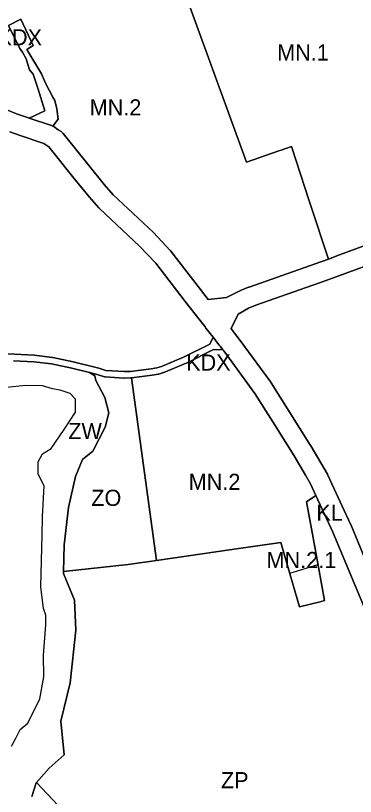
# Model space of a CAD drawing. Extents: x 7431767 to 7433133, y 5549450 to 5550702.
# Drawn here: x 7432224.9 to 7432434.9, y 5549892.8 to 5550375.6 of the extents above; entities that cross this region are included whole.
import ezdxf

# ---------------------------------------------------------------- set-up
doc = ezdxf.new("R2010")
doc.units = 0
for name, color, linetype in [('linie_rozgraniczajace', 7, 'Continuous'), ('nieprzekraczalne_linie_zabudowy', 7, 'Continuous'), ('oznaczenia_przeznaczen', 7, 'Continuous')]:
    doc.layers.add(name, color=color, linetype=linetype)

msp = doc.modelspace()

# ---------------------------------------------------------------- linework, layer by layer
at = {"layer": 'linie_rozgraniczajace'}
for points in [[(7432324.79, 5550402.95), (7432367.6, 5550285.01), (7432387.65, 5550291.96), (7432389, 5550292.48), (7432395.45, 5550294.68), (7432406.26, 5550261.15), (7432418.17, 5550225.09), (7432410.03, 5550222.13), (7432369.14, 5550207.78), (7432368.84, 5550207.66), (7432363.79, 5550205.54), (7432363.61, 5550205.45), (7432363.12, 5550205.2), (7432355.18, 5550201.22), (7432343.93, 5550200.14), (7432339.15, 5550206.28), (7432320.83, 5550229.98), (7432320.57, 5550230.29), (7432320.47, 5550230.4), (7432310.2, 5550241.47), (7432310.04, 5550241.57), (7432309.91, 5550241.77), (7432285.14, 5550264.86), (7432279.66, 5550271.15), (7432270.25, 5550282.69), (7432254.3, 5550302.65), (7432253.68, 5550303.31), (7432253, 5550303.85), (7432251.27, 5550305.05), (7432248.53, 5550306.94), (7432247.86, 5550307.3), (7432251.1, 5550311.5), (7432250.4, 5550317.93), (7432249.03, 5550323.1), (7432247.98, 5550325.07), (7432243.38, 5550333.82), (7432240.92, 5550339.61), (7432231.81, 5550354.58), (7432235.73, 5550357.2), (7432228.13, 5550373.41), (7432220.5, 5550369.5), (7432227.46, 5550355.28), (7432229.18, 5550353.02), (7432231.35, 5550348.97), (7432233.41, 5550342.08), (7432235.68, 5550339.37), (7432238.59, 5550330.8), (7432242.97, 5550316.77), (7432233.24, 5550312.23), (7432231.53, 5550312.79), (7432225.41, 5550314.91), (7432219.55, 5550317.43)], [(7432441.37, 5550233.57), (7432425.1, 5550227.62), (7432418.17, 5550225.09), (7432406.26, 5550261.15), (7432395.45, 5550294.68), (7432389, 5550292.48), (7432387.65, 5550291.96), (7432367.6, 5550285.01), (7432324.79, 5550402.95)], [(7432219.55, 5550317.43), (7432225.41, 5550314.91), (7432231.53, 5550312.79), (7432233.24, 5550312.23), (7432247.06, 5550307.65), (7432247.86, 5550307.3), (7432248.53, 5550306.94), (7432251.27, 5550305.05), (7432253, 5550303.85), (7432253.68, 5550303.31), (7432254.3, 5550302.65), (7432270.25, 5550282.69), (7432279.66, 5550271.15), (7432285.14, 5550264.86), (7432309.91, 5550241.77), (7432310.04, 5550241.57), (7432310.2, 5550241.47), (7432320.47, 5550230.4), (7432320.57, 5550230.29)], [(7432221.27, 5550303.64), (7432227.64, 5550301.44), (7432242.42, 5550296.57), (7432245.47, 5550294.46), (7432260.89, 5550275.17), (7432270.43, 5550263.49), (7432270.53, 5550263.4), (7432276.28, 5550256.75), (7432276.7, 5550256.31), (7432301.56, 5550233.14), (7432311.51, 5550222.43), (7432329.66, 5550198.92), (7432341.17, 5550184.28), (7432341.99, 5550183.21), (7432342.53, 5550182.4), (7432346.91, 5550176.76), (7432344.87, 5550172.53), (7432328.69, 5550164.34), (7432314.97, 5550158.64), (7432312.25, 5550157.75), (7432308.68, 5550157.2), (7432295.92, 5550155.63), (7432291.89, 5550155.47), (7432280.73, 5550156.25), (7432276.36, 5550157.51), (7432260.53, 5550161.53), (7432247.85, 5550164.21), (7432247.69, 5550164.24), (7432236.38, 5550165.6), (7432220.02, 5550166.42)], [(7432420.95, 5550056.23), (7432410.46, 5550078.85), (7432407.07, 5550086.17), (7432403.98, 5550091.44), (7432396.96, 5550103.47), (7432383.88, 5550124.43), (7432372.75, 5550141.96), (7432353.55, 5550168.26), (7432353.02, 5550168.97), (7432351.3, 5550171.29), (7432350.68, 5550171.93), (7432348.7, 5550174.47), (7432346.91, 5550176.76), (7432342.53, 5550182.4), (7432341.99, 5550183.21), (7432341.17, 5550184.28), (7432329.66, 5550198.92), (7432311.51, 5550222.43), (7432301.56, 5550233.14), (7432276.7, 5550256.31), (7432276.28, 5550256.75), (7432270.53, 5550263.4), (7432270.43, 5550263.49), (7432260.89, 5550275.17), (7432245.47, 5550294.46), (7432242.42, 5550296.57), (7432227.64, 5550301.44), (7432221.27, 5550303.64)], [(7432320.57, 5550230.29), (7432320.83, 5550229.98), (7432339.15, 5550206.28), (7432343.93, 5550200.14), (7432355.18, 5550201.22), (7432363.12, 5550205.2), (7432363.61, 5550205.45), (7432363.79, 5550205.54), (7432368.84, 5550207.66), (7432369.14, 5550207.78), (7432410.03, 5550222.13), (7432418.17, 5550225.09), (7432425.1, 5550227.62), (7432441.37, 5550233.57)], [(7432445.39, 5550222.28), (7432416.21, 5550211.58), (7432373.29, 5550196.52), (7432368.8, 5550194.63), (7432362.38, 5550190.91), (7432358.05, 5550182.04), (7432359.57, 5550180.09), (7432360.17, 5550179.31), (7432363.1, 5550175.49), (7432382.57, 5550148.88), (7432382.67, 5550148.68), (7432382.77, 5550148.55), (7432394.03, 5550130.84), (7432407.21, 5550109.75), (7432407.28, 5550109.6), (7432417.56, 5550091.97), (7432417.83, 5550091.48), (7432431.88, 5550061.17), (7432431.99, 5550060.95), (7432450.91, 5550015.4)], [(7432450.91, 5550015.4), (7432431.99, 5550060.95), (7432431.88, 5550061.17), (7432417.83, 5550091.48), (7432417.56, 5550091.97), (7432407.28, 5550109.6), (7432407.21, 5550109.75), (7432394.03, 5550130.84), (7432382.77, 5550148.55), (7432382.67, 5550148.68), (7432382.57, 5550148.88), (7432363.1, 5550175.49), (7432360.17, 5550179.31), (7432359.57, 5550180.09), (7432358.05, 5550182.04), (7432362.38, 5550190.91), (7432368.8, 5550194.63), (7432373.29, 5550196.52), (7432416.21, 5550211.58), (7432445.39, 5550222.28)], [(7432220.02, 5550166.42), (7432236.38, 5550165.6), (7432247.69, 5550164.24), (7432247.85, 5550164.21), (7432260.53, 5550161.53), (7432276.36, 5550157.51), (7432280.73, 5550156.25), (7432291.89, 5550155.47), (7432295.92, 5550155.63), (7432308.68, 5550157.2), (7432312.25, 5550157.75), (7432314.97, 5550158.64), (7432328.69, 5550164.34), (7432344.87, 5550172.53), (7432346.91, 5550176.76), (7432348.7, 5550174.47), (7432350.68, 5550171.93), (7432351.3, 5550171.29), (7432353.02, 5550168.97), (7432347.13, 5550169.19), (7432330.43, 5550160.73), (7432330.27, 5550160.67), (7432316.43, 5550154.92), (7432316.28, 5550154.86), (7432313.35, 5550153.9), (7432313.19, 5550153.87), (7432313.04, 5550153.82), (7432309.25, 5550153.24), (7432296.46, 5550151.67), (7432296.18, 5550151.64), (7432291.93, 5550151.47), (7432291.71, 5550151.47), (7432280.23, 5550152.28), (7432279.98, 5550152.33), (7432279.82, 5550152.35), (7432275.36, 5550153.64), (7432270.53, 5550154.87), (7432259.59, 5550157.64), (7432247.1, 5550160.28), (7432236.1, 5550161.61), (7432223.5, 5550162.24)], [(7432223.5, 5550162.24), (7432236.1, 5550161.61), (7432247.1, 5550160.28), (7432259.59, 5550157.64), (7432270.53, 5550154.87), (7432273.89, 5550152.78), (7432274.44, 5550150.05), (7432279.94, 5550139.47), (7432282.45, 5550130.04), (7432280.28, 5550121.06), (7432272.71, 5550106.34), (7432266.14, 5550101.2), (7432261.9, 5550090.65), (7432257.62, 5550071.42), (7432254.83, 5550048.43), (7432254.53, 5550031.87), (7432254.49, 5550030.62), (7432261.32, 5550014.16), (7432262.17, 5549995.55), (7432258.61, 5549963), (7432252.91, 5549939.26), (7432254.81, 5549918.58), (7432245.61, 5549910.37), (7432237.84, 5549901.52), (7432237.51, 5549901.14), (7432235, 5549892.77)], [(7432222.29, 5549923.94), (7432225.13, 5549928.83), (7432227.63, 5549934.18), (7432232.5, 5549938.16), (7432239.96, 5549953.2), (7432242.26, 5549966.74), (7432242.21, 5549980.17), (7432243.58, 5549998.98), (7432243.49, 5550004.95), (7432242.1, 5550009.08), (7432240.47, 5550022.47), (7432240.65, 5550030.34), (7432241.23, 5550054.59), (7432241.46, 5550065.69), (7432242.5, 5550084.91), (7432238.92, 5550092.16), (7432238.74, 5550099.76), (7432241.45, 5550104.59), (7432246.91, 5550107.9), (7432254.85, 5550119.64), (7432261.82, 5550130.47), (7432261.91, 5550138.37), (7432258.67, 5550141.97), (7432252.52, 5550143.97), (7432247.73, 5550144.89), (7432241.58, 5550146.77), (7432230.98, 5550146.87), (7432213.32, 5550145.08)], [(7432274.77, 5549862.2), (7432237.84, 5549901.52), (7432245.61, 5549910.37), (7432254.81, 5549918.58), (7432252.91, 5549939.26), (7432258.61, 5549963), (7432262.17, 5549995.55), (7432261.32, 5550014.16), (7432254.49, 5550030.62), (7432254.53, 5550031.87), (7432294.42, 5550036.26), (7432311.98, 5550038.77), (7432358.53, 5550045.43), (7432388.72, 5550049.82), (7432394.57, 5550029.82), (7432400.34, 5550010.06), (7432413.13, 5550013.2), (7432415.85, 5550013.87), (7432412.07, 5550034.62), (7432408.74, 5550052.74), (7432404.68, 5550075.05), (7432410.46, 5550078.85), (7432420.95, 5550056.23), (7432439.81, 5550010.85)], [(7432483.35, 5549887.26), (7432480.75, 5549898.9), (7432479.4, 5549904.39), (7432478.73, 5549907.09), (7432476.07, 5549917.85), (7432467.96, 5549939.81), (7432459.33, 5549961.38), (7432453.65, 5549975.53), (7432439.81, 5550010.85), (7432420.95, 5550056.23)], [(7432235, 5549892.77), (7432237.51, 5549901.14), (7432237.84, 5549901.52), (7432274.77, 5549862.2)]]:
    msp.add_lwpolyline(points, dxfattribs=at)
for points in [[(7432233.24, 5550312.23), (7432242.97, 5550316.77), (7432238.59, 5550330.8), (7432235.68, 5550339.37), (7432233.41, 5550342.08), (7432231.35, 5550348.97), (7432229.18, 5550353.02), (7432227.46, 5550355.28), (7432220.5, 5550369.5), (7432228.13, 5550373.41), (7432235.73, 5550357.2), (7432231.81, 5550354.58), (7432240.92, 5550339.61), (7432243.38, 5550333.82), (7432247.98, 5550325.07), (7432249.03, 5550323.1), (7432250.4, 5550317.93), (7432251.1, 5550311.5), (7432247.86, 5550307.3), (7432247.06, 5550307.65)], [(7432296.46, 5550151.67), (7432309.25, 5550153.24), (7432313.04, 5550153.82), (7432313.19, 5550153.87), (7432313.35, 5550153.9), (7432316.28, 5550154.86), (7432316.43, 5550154.92), (7432330.27, 5550160.67), (7432330.43, 5550160.73), (7432347.13, 5550169.19), (7432353.02, 5550168.97), (7432353.55, 5550168.26), (7432372.75, 5550141.96), (7432383.88, 5550124.43), (7432396.96, 5550103.47), (7432403.98, 5550091.44), (7432407.07, 5550086.17), (7432410.46, 5550078.85), (7432404.68, 5550075.05), (7432408.74, 5550052.74), (7432412.07, 5550034.62), (7432415.85, 5550013.87), (7432413.13, 5550013.2), (7432400.34, 5550010.06), (7432394.57, 5550029.82), (7432388.72, 5550049.82), (7432358.53, 5550045.43), (7432311.98, 5550038.77)], [(7432270.53, 5550154.87), (7432275.36, 5550153.64), (7432279.82, 5550152.35), (7432279.98, 5550152.33), (7432280.23, 5550152.28), (7432291.71, 5550151.47), (7432291.93, 5550151.47), (7432296.18, 5550151.64), (7432296.46, 5550151.67), (7432311.98, 5550038.77), (7432294.42, 5550036.26), (7432254.53, 5550031.87), (7432254.83, 5550048.43), (7432257.62, 5550071.42), (7432261.9, 5550090.65), (7432266.14, 5550101.2), (7432272.71, 5550106.34), (7432280.28, 5550121.06), (7432282.45, 5550130.04), (7432279.94, 5550139.47), (7432274.44, 5550150.05), (7432273.89, 5550152.78)]]:
    msp.add_lwpolyline(points, close=True, dxfattribs=at)
at = {"layer": 'nieprzekraczalne_linie_zabudowy'}
msp.add_lwpolyline([(7432394.27, 5550030.87), (7432411.8, 5550036.14)], dxfattribs=at)

# ---------------------------------------------------------------- texts
at = {"layer": 'oznaczenia_przeznaczen'}
for s, p in [('KDX', (7432213.73, 5550357.2)), ('MN.1', (7432386.53, 5550347.83)), ('MN.2', (7432270.64, 5550313.84)), ('KDX', (7432330.29, 5550156.07)), ('ZW', (7432257.43, 5550113.73)), ('MN.2', (7432331.85, 5550082.33)), ('ZO', (7432271.65, 5550072.43)), ('KL', (7432410.78, 5550063.31)), ('MN.2.1', (7432379.95, 5550033.97)), ('ZP', (7432351.78, 5549897.85))]:
    msp.add_text(s, height=10, dxfattribs=at).set_placement(p)

doc.saveas('drawing.dxf')
